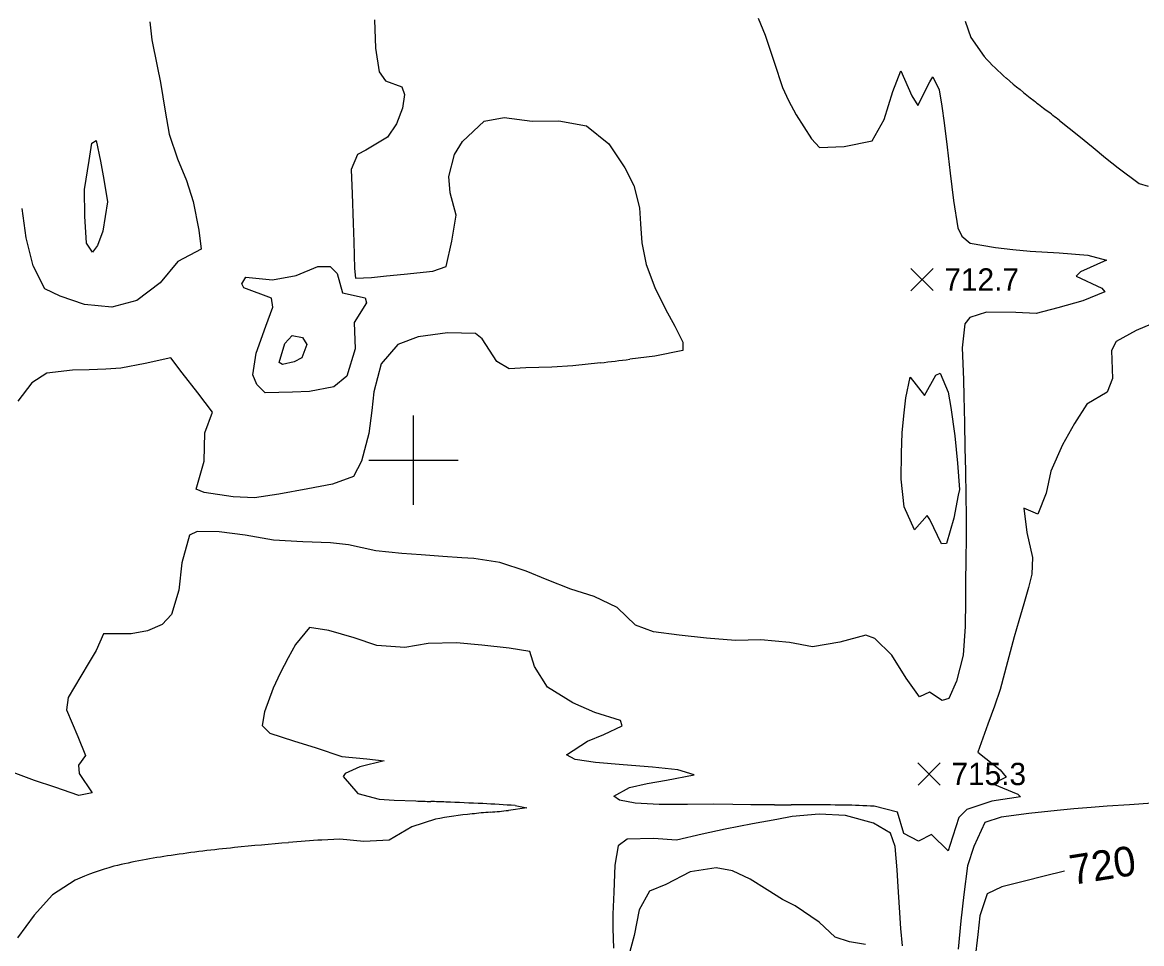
# Model space of a CAD drawing. Extents: x 2566079 to 2571326, y 424054 to 426896.
# Drawn here: x 2568737 to 2569490, y 424675 to 425294 of the extents above; entities that cross this region are included whole.
import ezdxf

# ---------------------------------------------------------------- set-up
doc = ezdxf.new("R2010")
doc.units = 0
for name, color, linetype in [('Contour_ADS_Label_Major', 7, 'Continuous'), ('Contour_ADS_Major', 7, 'Continuous'), ('Contour_ADS_Minor', 7, 'Continuous'), ('Contour_ADS_Spot_Elevation', 7, 'Continuous'), ('Contour_ADS_Tick', 7, 'Continuous')]:
    doc.layers.add(name, color=color, linetype=linetype)

# ---------------------------------------------------------------- blocks, each defined once
blk = doc.blocks.new('S890')
at = {"layer": 'Contour_ADS_Tick'}
for p, q in [((0, -0.5), (0, 0.5)), ((-0.5, 0), (0.5, 0))]:
    blk.add_line(p, q, dxfattribs=at)
blk = doc.blocks.new('S750')
at = {"layer": 'Contour_ADS_Spot_Elevation'}
for p, q in [((-0.5, 0.498), (0.5, -0.498)), ((-0.498, -0.5), (0.498, 0.5))]:
    blk.add_line(p, q, dxfattribs=at)

msp = doc.modelspace()

# ---------------------------------------------------------------- linework, layer by layer
at = {"layer": 'Contour_ADS_Major'}
for points in [[(2568822.76, 425294.56), (2568824.15, 425282.58), (2568827.76, 425264.8), (2568829.94, 425253.84)], [(2568829.94, 425253.84), (2568833.02, 425234.58), (2568835.71, 425219.17), (2568841.39, 425202.52), (2568847.29, 425188.04), (2568851.82, 425173.79), (2568855.64, 425154.57), (2568857.3, 425141.91), (2568841.46, 425133.41), (2568829.79, 425119.12), (2568814.08, 425107.34), (2568797.22, 425102.83), (2568778.83, 425104.64), (2568762.51, 425110.14), (2568752.19, 425115.06), (2568744.34, 425130.5), (2568739.53, 425149.51), (2568736.86, 425169.21)], [(2569304.06, 424674.2), (2569293.31, 424676.06), (2569283.72, 424679.27), (2569272.8, 424689.37), (2569256.79, 424700.2), (2569248.23, 424704.46), (2569237.84, 424711.02), (2569226.36, 424718.22), (2569214.69, 424723.77), (2569203.68, 424725.94), (2569186.15, 424723.19), (2569169.71, 424714.68), (2569158.71, 424710.16), (2569151.89, 424697.5), (2569148.4, 424680.26), (2569143.26, 424661.28)], [(2569437.82, 424723.6), (2569424.08, 424720.13), (2569410.99, 424716.84), (2569395.73, 424712.98), (2569385.95, 424708.44), (2569380.91, 424693.53), (2569379.5, 424681), (2569377.6, 424663.89)]]:
    msp.add_lwpolyline(points, dxfattribs=at)
msp.add_lwpolyline([(2568894.6, 425050.89), (2568892.08, 425057.42), (2568894.3, 425071.93), (2568900.86, 425090.08), (2568905.55, 425102.72), (2568904.54, 425108.78), (2568885.89, 425115.79), (2568884.52, 425118.58), (2568887.24, 425122.99), (2568905.16, 425121.22), (2568921.06, 425124.18), (2568935.83, 425130.06), (2568944.06, 425130.22), (2568948.71, 425125.38), (2568952.39, 425112.42), (2568967.5, 425109.15), (2568968.53, 425105.75), (2568960.07, 425092.55), (2568960.92, 425074.85), (2568955.19, 425056.43), (2568946.47, 425049.18), (2568930.14, 425046.1), (2568918.73, 425045.64), (2568900.32, 425045.31), (2568894.6, 425050.89)], close=True, dxfattribs=at)
at = {"layer": 'Contour_ADS_Minor'}
for points in [[(2568973.94, 425296.11), (2568974.54, 425277.01), (2568977.05, 425261.06), (2568981.2, 425255.01), (2568992.25, 425250.98), (2568994.04, 425245.7), (2568992.73, 425236.69), (2568988.67, 425226.19), (2568982.57, 425217.14), (2568968.07, 425208.44), (2568962.38, 425205.39), (2568958.09, 425195.38), (2568958.73, 425179.08), (2568959.51, 425159.37), (2568959.82, 425146.66), (2568960.34, 425128.86), (2568961.08, 425122.29), (2568971.77, 425122.75), (2568981.98, 425123.79), (2568993.73, 425125), (2569013.12, 425127.04), (2569022.09, 425130.05), (2569025.94, 425147.2), (2569028.77, 425164.78), (2569024.68, 425179.64), (2569023.76, 425190.58), (2569027.69, 425205.56), (2569033.08, 425214.19), (2569047.52, 425227.91), (2569061.08, 425230.44), (2569079.88, 425227.96), (2569097.79, 425228), (2569116.47, 425224.75), (2569131.35, 425212.68), (2569142.2, 425196.51), (2569148.13, 425184.71), (2569151.95, 425169.6), (2569152.61, 425158.88), (2569153.65, 425146.05), (2569156.6, 425131.55), (2569162.39, 425116.11), (2569169.48, 425101.55), (2569175.73, 425090.01), (2569181.2, 425079.28), (2569181.22, 425073.77), (2569162.38, 425069.87), (2569145.63, 425067.8)], [(2569231.77, 425297.06), (2569236.61, 425285.72), (2569242.61, 425267.5), (2569248.13, 425250.61), (2569252.25, 425241.81), (2569257.47, 425232.24), (2569267.66, 425216.06)], [(2569371.09, 425295.08), (2569374.97, 425284.15), (2569383.82, 425271.35)], [(2569267.66, 425216.06), (2569273.02, 425210.1), (2569289.68, 425210.94), (2569308.5, 425214.63), (2569316.66, 425228.89), (2569322.51, 425247.85), (2569327.83, 425261.63), (2569335.17, 425244.98), (2569339.2, 425238.32), (2569347.28, 425254.35), (2569349.31, 425257.59), (2569353.46, 425248.96), (2569355.39, 425238.03), (2569356.98, 425226.85), (2569358.95, 425210.31), (2569360.96, 425192.99), (2569363.31, 425174.62), (2569366.21, 425156.2), (2569368.8, 425150.5), (2569374.46, 425145.85), (2569391.5, 425142.83), (2569403.07, 425141.52), (2569414.79, 425140.46), (2569434.35, 425139.44), (2569453.63, 425137.78), (2569466.21, 425134.47), (2569448.7, 425126.51), (2569445.79, 425123.59), (2569462.96, 425115.65), (2569464.96, 425113.22), (2569450.13, 425107), (2569433.4, 425102.39), (2569418.79, 425098.47), (2569405.03, 425099.22), (2569385.4, 425099.48), (2569374.14, 425095.84), (2569370.85, 425091.57), (2569369.14, 425075.45), (2569369.53, 425064.93), (2569369.9, 425053.85), (2569370.15, 425043.01), (2569370.53, 425025.05), (2569370.94, 425008.16), (2569371.26, 424992.83), (2569371.56, 424975.71), (2569371.69, 424962.65), (2569371.72, 424947.92), (2569371.59, 424932.63), (2569371.37, 424918.05), (2569371.18, 424905.44), (2569371.03, 424888.1), (2569369.72, 424868.81), (2569365.16, 424851.41), (2569360.15, 424839.65), (2569355.67, 424838.32), (2569347.06, 424844.03), (2569340.36, 424840.72), (2569331.36, 424853.32), (2569321.72, 424868.8), (2569310.24, 424879.93), (2569304.15, 424882.18), (2569286.75, 424877.48), (2569268.3, 424874.46), (2569252.99, 424877.33), (2569233.65, 424879.05), (2569216.71, 424878.64), (2569197.21, 424880.26), (2569178.77, 424882.32), (2569161.51, 424884.63), (2569149.34, 424888.91), (2569136.95, 424900.86), (2569121.56, 424908.39), (2569105.97, 424913.13), (2569090.05, 424919.58), (2569075.88, 424925.39), (2569058.06, 424931.09), (2569040.71, 424933.89), (2569032.63, 424934.31), (2569019.87, 424935.16), (2569005.12, 424936.23), (2568992.1, 424937.23), (2568974.82, 424939.07), (2568956.43, 424942.97), (2568944.21, 424944.27), (2568925.72, 424945.02), (2568905.87, 424946.19), (2568886.88, 424949.57), (2568869.31, 424951.79), (2568854.47, 424951.96), (2568849.52, 424949.44), (2568844.35, 424930.94), (2568842.3, 424912.53), (2568837.41, 424896.13), (2568831.09, 424889.44), (2568821.25, 424885.23), (2568810.12, 424883.15), (2568791.56, 424883.27), (2568786.72, 424872.01), (2568781.97, 424864.06), (2568776.32, 424854.63), (2568767.82, 424840.47)], [(2569434.41, 425228.37), (2569447.44, 425218.11), (2569457.17, 425210.16), (2569465.52, 425203.25), (2569473.92, 425196.45), (2569488.05, 425186.03), (2569494.18, 425184.27)], [(2569496.09, 425091.32), (2569485.98, 425087.08), (2569472.55, 425079.72), (2569469.53, 425073.66), (2569470.18, 425054.9), (2569466.62, 425045.66), (2569452.91, 425037.63), (2569444.5, 425024.68), (2569436.52, 425010.28), (2569428.66, 424992.54), (2569425.6, 424977.72), (2569419.96, 424963.61), (2569410.41, 424967.61), (2569412.56, 424951.25), (2569416.27, 424934.45), (2569415.83, 424923.2), (2569413.61, 424914.32), (2569410.49, 424903.41), (2569407.11, 424891.95), (2569404.01, 424881.22), (2569399.53, 424864.39), (2569394.69, 424845.65), (2569390.79, 424834.61), (2569386.26, 424822.41), (2569379.67, 424803.6), (2569394.69, 424791.82), (2569398.69, 424786.86), (2569389.64, 424782.31), (2569406.41, 424775.47), (2569408.32, 424773.66), (2569388.89, 424770.72), (2569372.22, 424765.1), (2569366.83, 424759.66), (2569360.74, 424740.78), (2569359.55, 424737.2), (2569348.5, 424748.33), (2569339.69, 424743.81), (2569329.7, 424748.96), (2569325.55, 424763.26), (2569309.93, 424767.24)], [(2569125.76, 425065.41), (2569107.13, 425063.48), (2569093.08, 425062.56), (2569075.68, 425062.04), (2569064.35, 425061.42), (2569056.17, 425066.28), (2569046.3, 425081.48), (2569041.68, 425085.17), (2569022.87, 425085.51), (2569003.12, 425082.81), (2568989.59, 425077.68), (2568978.32, 425064.66), (2568973.4, 425045.96), (2568971.93, 425033.25), (2568970.01, 425017.86), (2568965.05, 424999.24), (2568959.77, 424989.07), (2568945.48, 424983.87), (2568928.98, 424980.74), (2568909.53, 424977.11), (2568893.14, 424974.56), (2568878.88, 424975.33), (2568859.18, 424978.2), (2568853.97, 424980.38), (2568859.33, 424999.35), (2568859.67, 425018.29), (2568864.96, 425032.24), (2568855.13, 425045.28), (2568844.46, 425058.56), (2568836.9, 425068.68), (2568819.55, 425064.89), (2568803.2, 425061.87), (2568793.09, 425061.04), (2568781.84, 425060.72), (2568770.63, 425060.53), (2568753.49, 425058.55), (2568743.29, 425052.04), (2568734, 425039.54)], [(2569242.77, 424768.17), (2569226.93, 424768.31), (2569214.79, 424768.5), (2569201.66, 424768.55), (2569184.31, 424768.4), (2569165.38, 424768.47), (2569149.02, 424769.29), (2569138.61, 424771.23), (2569134.72, 424773.96), (2569145.33, 424779.85), (2569157.17, 424782.46), (2569170.17, 424784.75), (2569188.77, 424788.45), (2569177.83, 424791.77), (2569160.75, 424793.45), (2569141, 424795.07), (2569122.52, 424796.69), (2569108.72, 424798.75), (2569102.88, 424801.79), (2569116.99, 424811.01), (2569128.16, 424815.53), (2569140.45, 424821.4), (2569139.24, 424824.85), (2569122.09, 424830.36), (2569107.18, 424836.86), (2569090.26, 424847.37), (2569081.52, 424861.25), (2569078.21, 424871.22), (2569064.43, 424873.56), (2569046.11, 424875.53), (2569028.89, 424877.09), (2569009.94, 424876.71), (2568994.24, 424873.97), (2568975.47, 424875.39), (2568960.05, 424880.42), (2568943.06, 424885.42), (2568930.19, 424887.47), (2568920.65, 424875.95), (2568915.81, 424867.09), (2568910.45, 424856.79), (2568905.62, 424846.59), (2568899.94, 424830.65), (2568898.25, 424821.52), (2568903.35, 424816.47), (2568919.26, 424811.14), (2568934.56, 424806.55), (2568951.83, 424800.76), (2568968.7, 424799.19), (2568980.37, 424797.88), (2568964.07, 424793.71), (2568954.17, 424789.31), (2568952.67, 424787.33), (2568962.63, 424775.84), (2568977.02, 424772), (2568987.16, 424771.38), (2569001.62, 424770.81)], [(2568767.82, 424840.47), (2568766.72, 424832.16), (2568774.27, 424814.06), (2568779.39, 424801.33), (2568774.8, 424794.79), (2568775.2, 424789.23), (2568783.93, 424776.24), (2568774.91, 424774.59), (2568758.93, 424780.12), (2568745.2, 424784.67), (2568729.03, 424790.6)], [(2569068.37, 424767.67), (2569076.3, 424766.15), (2569063.93, 424764.45)], [(2569497.01, 424769.36), (2569481.64, 424768.19), (2569466.66, 424767.33), (2569455.73, 424766.52), (2569444.11, 424765.53), (2569433.01, 424764.46), (2569413.84, 424762.36), (2569395.34, 424759.92), (2569384.21, 424756.28), (2569376.8, 424740.09), (2569372.72, 424727.2), (2569370.08, 424707.87), (2569368.25, 424690.31), (2569366.25, 424671.12)], [(2569328.88, 424673.45), (2569327.82, 424685.09), (2569326.9, 424699.25), (2569326.11, 424713.17), (2569325.43, 424724.61), (2569324.08, 424740.18), (2569320.94, 424749.05), (2569309.45, 424755.79), (2569290.53, 424760.93), (2569272.87, 424761.98), (2569254.63, 424760.29), (2569244.29, 424758.45), (2569228.11, 424755.39), (2569209.72, 424751.77), (2569194.08, 424748.46), (2569176.97, 424744.38), (2569161.37, 424745.49), (2569143.8, 424745.15), (2569137.74, 424740.72), (2569135.44, 424727.53), (2569134.69, 424709.4), (2569134.16, 424694.63), (2569134.16, 424685.01), (2569134.46, 424671.9)], [(2569014.78, 424758.52), (2568999.02, 424753.5), (2568983.64, 424744.44), (2568966.6, 424743.58), (2568950.41, 424745.05), (2568938.48, 424744.54)], [(2568772.44, 424717.45), (2568757.18, 424707.59), (2568745.04, 424694.1), (2568733.81, 424678.88)]]:
    msp.add_lwpolyline(points, dxfattribs=at)
for points in [[(2568791.72, 425188.59), (2568794.36, 425173.53), (2568791.06, 425154.02), (2568787.47, 425144.24), (2568784.26, 425139.89), (2568780.04, 425145.82), (2568779.07, 425163.97), (2568778.74, 425181.85), (2568781.85, 425201.41), (2568783.76, 425213.05), (2568786.59, 425214.91), (2568789.63, 425200.87), (2568791.72, 425188.59)], [(2568919.91, 425066.09), (2568911.99, 425064.18), (2568909.68, 425065.58), (2568913.63, 425078.49), (2568918.39, 425083.77), (2568925.45, 425082.38), (2568928.39, 425077.67), (2568924.92, 425068.81), (2568919.91, 425066.09)], [(2569366.46, 424976.33), (2569363.35, 424960.91), (2569358.58, 424943.82), (2569355.05, 424943.67), (2569347.23, 424960.07), (2569345.49, 424962.76), (2569337.04, 424953.04), (2569329.98, 424968.55), (2569328.08, 424987.2), (2569328.23, 425004.7), (2569328.79, 425018.24), (2569329.82, 425029.71), (2569331.21, 425041.84), (2569334.1, 425055.74), (2569343.82, 425043.41), (2569351.3, 425057.15), (2569354.3, 425058.41), (2569359.52, 425045.66), (2569361.52, 425035.37), (2569364.08, 425016.4), (2569365.8, 424997.92), (2569367.2, 424980.33), (2569366.46, 424976.33)]]:
    msp.add_lwpolyline(points, close=True, dxfattribs=at)
for centre, radius, start, end in [((2569516.54, 425392.85), 179.94, 222.47382, 229.18124), ((2569744.12, 425658.85), 530.01, 229.35876, 231.91222), ((2569907.04, 425866.1), 793.62, 231.88443, 232.67029), ((2568087.51, 423496.6), 2193.89, 52.12562, 52.41027), ((2568720.48, 428518.65), 3476.94, 276.69379, 277.02359), ((2569232.8, 430907.54), 6141.09, 267.842589, 267.936325), ((2568867.73, 420728.39), 4044.61, 87.8183, 87.96062), ((2568923.11, 422144.82), 2627.1, 87.30269, 87.84929), ((2569016.57, 424106.75), 662.94, 85.51846, 87.39154), ((2569246.41, 426966.21), 2198.04, 269.90501, 270.19722), ((2569259.58, 421508.58), 3259.61, 89.90157, 90.09844), ((2569263.58, 422772.35), 1995.83, 89.25076, 89.95413), ((2569284.3, 424359.91), 408.13, 86.39981, 89.24498), ((2569073.01, 424443.96), 319.91, 96.01978, 100.48737), ((2569094.88, 424251.68), 513.42, 94.82548, 96.19666), ((2569014.61, 425215.84), 454.08, 274.68444, 276.23599), ((2569038.65, 423333.53), 1414.56, 94.06073, 94.97126), ((2568975.88, 423773.78), 970.43, 95.68667, 98.22248), ((2569066.85, 422902.31), 1846.62, 94.68354, 95.81616), ((2568894.79, 424327.99), 410.31, 98.08431, 103.5541), ((2568838.71, 424574.48), 157.58, 104.73483, 114.86912)]:
    msp.add_arc(centre, radius, start, end, dxfattribs=at)

# ---------------------------------------------------------------- block references
at = {"layer": 'Contour_ADS_Spot_Elevation', "xscale": 15, "yscale": 15}
for p in [(2569342.06, 425121.41), (2569346.81, 424788.95)]:
    msp.add_blockref('S750', p, dxfattribs=at)
at = {"layer": 'Contour_ADS_Tick', "xscale": 60, "yscale": 60}
msp.add_blockref('S890', (2569000, 425000), dxfattribs=at)

# ---------------------------------------------------------------- texts
at = {"layer": 'Contour_ADS_Label_Major'}
msp.add_text('720', height=20, rotation=9.02644, dxfattribs=at).set_placement((2569442.95, 424714.29))
at = {"layer": 'Contour_ADS_Spot_Elevation'}
for s, p in [('712.7', (2569357.06, 425113.91)), ('715.3', (2569361.81, 424781.45))]:
    msp.add_text(s, height=15, dxfattribs=at).set_placement(p)

doc.saveas('drawing.dxf')
